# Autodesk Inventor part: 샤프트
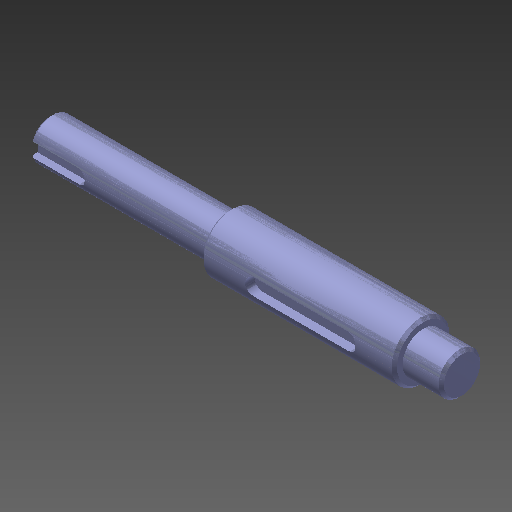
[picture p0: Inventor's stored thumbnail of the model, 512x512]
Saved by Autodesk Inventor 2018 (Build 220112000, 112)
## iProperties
Created: 2013-07
Part Number: 샤프트
Document SubType Name: Modeling
Designer: SeoGD™[esajin.kr]
Density: 7.86 g/cm^3
Mass: 291.771 g
Surface Area: 92.3634 cm^2
Volume: 37.1209 cm^3
Material: 강철, 연강
Appearance: 강철(1)
Author: SeoGD™[esajin.kr]
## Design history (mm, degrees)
sketch "스케치1"
  geometry: L1 (48, 37.7)-(48, 10.3) reference; L2 (35, 9.938)-(35, 54) reference; L3 (-35, 54)-(-35, 9.938) reference; L4 (-48, 37.7)-(-48, 10.3) reference; L5 (-70, 6.645)-(-70, 41.355) reference; L6 (-100, 24)-(49, 24); L7 (49, 24)-(49, 31.5); L8 (49, 31.5)-(35, 31.5); L9 (35, 31.5)-(35, 34.5); L10 (35, 34.5)-(-35, 34.5); L11 (-35, 34.5)-(-35, 31.5); L12 (-35, 31.5)-(-100, 31.5); L13 (-100, 31.5)-(-100, 24); 2 further points
  constraints: 16 end point, 5 perpendicular, 5 point on line, 1 collinear, 1 midpoint, 1 parallel
  dimensions: "d1" = 15 diameter of L12 L6; "d2" = 21 diameter of L10 L6; "d3" = 1 distance between parallel lines of L7 L1; "d4" = 30 distance between parallel lines of L13 L5
revolve "회전1" sketch "스케치1" stored, may be unused: angle "d5" = 90 deg
node "작업 평면1"
sketch "스케치2"
  geometry: L1 (35, -10.5)-(35, 10.5) reference; L2 (-16, -3)-(18, -3); L3 (18, 3)-(-16, 3); A1 r 3 centre (18, 0) between (18, -3) and (18, 3); A2 r 3 centre (-16, 0) between (-16, 3) and (-16, -3); 2 further points
  constraints: 4 end point, 4 point on circle, 4 tangent, 2 centre point, 1 horizontal alignment, 1 midpoint, 1 parallel, 1 perpendicular
  dimensions: "d6" = 6 distance between parallel lines of L2 L3; "d7" = 40 dimension on A1 A2; "d8" = 14 distance edge to line of A1 L1
extrude "돌출1" cut sketch "스케치2" distance "d9" = 3.5; taper "d10" = 0 deg
chamfer "모따기1" distance "d11" = 1; stored, may be unused: second distance "d12" = 2, angle "d13" = 45 deg
node "작업 평면2"
sketch "스케치3"
  geometry: L1 (-32.5, -6.5)-(-32.5, 6.5) reference; L2 (-32.5, 2.5)-(-15, 2.5); L3 (-15, -2.5)-(-32.5, -2.5); A1 r 2.5 centre (-15, 0) between (-15, -2.5) and (-15, 2.5); 2 further points
  constraints: 4 end point, 2 perpendicular, 2 point on circle, 2 point on line, 2 tangent, 1 centre point, 1 horizontal alignment, 1 midpoint
  dimensions: "d14" = 5 distance between parallel lines of L3 L2; "d15" = 20 dimension on A1 L1
extrude "돌출2" cut sketch "스케치3" distance "d16" = 3; taper "d17" = 0 deg
node "솔리드1"
node "참조1"
node "참조2"
node "참조3"
node "참조4"
node "참조5"
